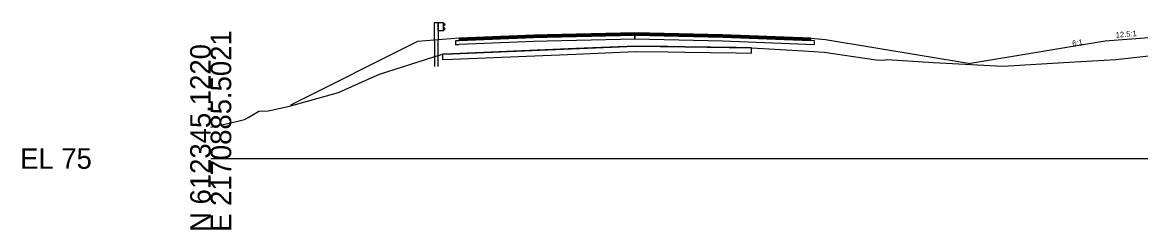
# Model space of a CAD drawing. Extents: x -26 to 1303, y -3010 to 12023.
# Drawn here: x -25.7 to 126.9, y 9990.3 to 10018.6 of the extents above; entities that cross this region are included whole.
import ezdxf

# ---------------------------------------------------------------- set-up
doc = ezdxf.new("R2010")
doc.units = 0
for name, color, linetype in [('RD_GPK_XS_Cell', 7, 'Continuous'), ('RD_PD_Final_TrvlWay', 7, 'Continuous'), ('RD_XS_Base', 7, 'Continuous'), ('RD_XS_ExGround', 7, 'Continuous'), ('RD_XS_ExPaveRet', 7, 'Continuous'), ('RD_XS_GR', 7, 'Continuous'), ('RD_XS_Greenside', 7, 'Continuous'), ('RD_XS_Pave', 7, 'Continuous'), ('RD_XS_PaveOvlay_CP', 7, 'Continuous'), ('RD_XS_TieSlope', 7, 'Continuous'), ('RD_XS_TX_ShdSlope', 7, 'Continuous'), ('RD_XS_TX_Slope', 7, 'Continuous')]:
    doc.layers.add(name, color=color, linetype=linetype)

msp = doc.modelspace()

# ---------------------------------------------------------------- linework, layer by layer
at = {"layer": 'RD_GPK_XS_Cell'}
msp.add_line((0, 10000), (150, 10000), dxfattribs=at)
at = {"layer": 'RD_PD_Final_TrvlWay'}
msp.add_lwpolyline([(31.04, 10012.56), (31.04, 10016.17), (30.54, 10016.13), (30.54, 10012.56)], dxfattribs=at)
at = {"layer": 'RD_XS_Base'}
for p, q in [((55.92, 10016.76), (45.88, 10016.56)), ((57.88, 10016.8), (55.92, 10016.76)), ((57.88, 10016.93), (57.88, 10016.96)), ((57.88, 10016.96), (57.88, 10016.85)), ((57.88, 10016.8), (57.88, 10016.96)), ((57.88, 10016.96), (57.88, 10016.96)), ((57.88, 10016.96), (57.88, 10016.96)), ((57.88, 10016.96), (57.88, 10016.3)), ((57.88, 10016.8), (57.88, 10016.93)), ((57.88, 10016.85), (57.88, 10016.3)), ((57.88, 10016.72), (57.88, 10016.8)), ((57.88, 10016.3), (57.88, 10016.8)), ((57.88, 10016.8), (57.88, 10016.8)), ((57.88, 10016.8), (57.88, 10016.8)), ((57.88, 10016.8), (57.88, 10016.8)), ((69.88, 10016.56), (57.88, 10016.8)), ((57.88, 10016.3), (57.88, 10016.72)), ((33.81, 10016.07), (33.38, 10016.06)), ((33.38, 10016.06), (33.38, 10015.99)), ((33.38, 10015.99), (33.38, 10015.56)), ((33.38, 10015.56), (33.81, 10015.57)), ((33.88, 10016.08), (33.81, 10016.07)), ((33.81, 10015.57), (33.88, 10015.58)), ((44.07, 10016.49), (33.88, 10016.08)), ((33.88, 10015.58), (44.07, 10015.99)), ((45.88, 10016.56), (44.07, 10016.49)), ((44.07, 10015.99), (45.88, 10016.06)), ((45.88, 10016.06), (55.92, 10016.26)), ((55.92, 10016.26), (57.88, 10016.3)), ((57.88, 10016.3), (57.88, 10016.3)), ((57.88, 10016.3), (57.88, 10016.3)), ((57.88, 10016.3), (69.88, 10016.06)), ((81.88, 10016.08), (69.88, 10016.56)), ((69.88, 10016.06), (82.38, 10015.56)), ((71.88, 10016.48), (71.88, 10016.48)), ((71.88, 10015.98), (71.88, 10015.98)), ((82.38, 10016.06), (81.88, 10016.08)), ((81.88, 10016.08), (81.88, 10016.08)), ((82.38, 10015.56), (82.38, 10016.06)), ((82.38, 10016.06), (82.38, 10016.06))]:
    msp.add_line(p, q, dxfattribs=at)
at = {"layer": 'RD_XS_ExGround'}
msp.add_lwpolyline([(0, 10004.26), (2.74, 10004.88), (4.59, 10005.3), (5.18, 10005.63), (6.58, 10006.44), (7.84, 10006.51), (10.76, 10007.15), (17.43, 10008.99), (21.07, 10010.64), (23.01, 10011.51), (30.42, 10013.87), (30.64, 10013.91), (31.6, 10014.23), (32.98, 10014.28), (57.91, 10015.34), (64.68, 10015.25), (73.79, 10015.11), (80.86, 10014.68), (83.68, 10014.5), (87.7, 10013.91), (90.78, 10013.47), (91.73, 10013.42), (92.27, 10013.49), (98.59, 10013.09), (108.04, 10012.6), (117.12, 10013.12), (123.46, 10013.5), (133.76, 10014.63)], dxfattribs=at)
at = {"layer": 'RD_XS_ExPaveRet'}
for points in [[(64.68, 10015.25), (62.37, 10015.28), (57.91, 10015.34), (49.83, 10015), (32.98, 10014.28), (31.6, 10014.23), (31.6, 10014.23), (31.6, 10014.23), (31.6, 10014.23), (31.6, 10013.91), (31.6, 10013.48), (31.6, 10013.48), (31.6, 10013.48), (31.6, 10013.48), (32.98, 10013.53), (49.83, 10014.25), (57.91, 10014.59), (62.37, 10014.53), (64.68, 10014.5), (71.7, 10014.39), (73.79, 10014.36), (73.79, 10014.55), (73.79, 10015.11), (71.7, 10015.14), (64.68, 10015.25)], [(64.68, 10015.25), (62.37, 10015.28), (57.91, 10015.34), (49.83, 10015), (32.98, 10014.28), (31.6, 10014.23), (31.6, 10014.23), (31.6, 10013.91), (31.6, 10013.48), (31.6, 10013.48), (32.98, 10013.53), (49.83, 10014.25), (57.91, 10014.59), (62.37, 10014.53), (64.68, 10014.5), (71.7, 10014.39), (73.79, 10014.36), (73.79, 10014.55), (73.79, 10015.11), (71.7, 10015.14), (64.68, 10015.25)]]:
    msp.add_lwpolyline(points, dxfattribs=at)
at = {"layer": 'RD_XS_GR'}
for p, q in [((30.54, 10016.13), (30.54, 10018.56)), ((30.54, 10018.56), (30.79, 10018.56)), ((30.79, 10018.56), (31.04, 10018.56)), ((31.04, 10018.56), (31.04, 10016.17)), ((31.04, 10017.4), (31.04, 10018.56)), ((31.04, 10018.56), (31.71, 10018.56)), ((31.71, 10018.56), (31.71, 10017.4)), ((31.75, 10018.52), (31.71, 10018.56)), ((31.71, 10018.56), (31.71, 10018.4)), ((31.71, 10018.4), (31.71, 10017.4)), ((31.71, 10017.98), (31.95, 10018.23)), ((31.98, 10018.27), (31.75, 10018.52)), ((31.95, 10018.23), (31.98, 10018.27)), ((31.71, 10017.4), (31.04, 10017.4)), ((31.75, 10017.94), (31.71, 10017.98)), ((31.71, 10017.4), (31.95, 10017.65)), ((31.98, 10017.69), (31.75, 10017.94)), ((31.95, 10017.65), (31.98, 10017.69)), ((31.04, 10016.17), (30.54, 10016.13))]:
    msp.add_line(p, q, dxfattribs=at)
at = {"layer": 'RD_XS_Greenside'}
for p, q in [((28.23, 10015.94), (10.9, 10007.28)), ((83.88, 10016.24), (103.67, 10012.94)), ((122, 10015.99), (103.67, 10012.94))]:
    msp.add_line(p, q, dxfattribs=at)
at = {"layer": 'RD_XS_Pave'}
for p, q in [((44.07, 10016.8), (33.88, 10016.4)), ((45.88, 10016.88), (44.07, 10016.8)), ((45.88, 10016.72), (44.07, 10016.64)), ((44.07, 10016.64), (45.88, 10016.72)), ((55.92, 10017.08), (45.88, 10016.88)), ((55.92, 10016.92), (45.88, 10016.72)), ((45.88, 10016.72), (55.92, 10016.92)), ((45.88, 10016.56), (55.92, 10016.76)), ((57.88, 10017.12), (55.92, 10017.08)), ((57.88, 10016.96), (55.92, 10016.92)), ((55.92, 10016.92), (57.88, 10016.96)), ((55.92, 10016.76), (57.88, 10016.8)), ((69.88, 10016.88), (57.88, 10017.12)), ((57.88, 10017.12), (57.88, 10017.12)), ((57.88, 10017.12), (57.88, 10017.12)), ((57.88, 10016.93), (57.88, 10016.96)), ((57.88, 10016.96), (57.88, 10016.93)), ((57.88, 10016.8), (57.88, 10016.96)), ((57.88, 10016.96), (57.88, 10016.96)), ((57.88, 10016.96), (57.88, 10016.96)), ((57.88, 10016.96), (57.88, 10016.96)), ((57.88, 10016.96), (57.88, 10016.96)), ((57.88, 10016.96), (69.88, 10016.72)), ((69.88, 10016.72), (57.88, 10016.96)), ((57.88, 10016.96), (57.88, 10016.96)), ((57.88, 10016.96), (57.88, 10016.96)), ((57.88, 10016.96), (57.88, 10016.8)), ((57.88, 10016.8), (57.88, 10016.93)), ((57.88, 10016.93), (57.88, 10016.8)), ((57.88, 10016.8), (57.88, 10016.8)), ((57.88, 10016.8), (57.88, 10016.8)), ((57.88, 10016.8), (69.88, 10016.56)), ((81.88, 10016.4), (69.88, 10016.88)), ((69.88, 10016.72), (81.88, 10016.24)), ((81.88, 10016.24), (69.88, 10016.72)), ((71.88, 10016.8), (71.88, 10016.8)), ((44.07, 10016.64), (33.88, 10016.24)), ((33.88, 10016.24), (44.07, 10016.64)), ((33.88, 10016.08), (44.07, 10016.49)), ((33.88, 10016.4), (33.88, 10016.37)), ((33.88, 10016.37), (33.88, 10016.24)), ((33.88, 10016.24), (33.88, 10016.21)), ((33.88, 10016.21), (33.88, 10016.08)), ((44.07, 10016.49), (45.88, 10016.56)), ((69.88, 10016.56), (81.88, 10016.08)), ((71.88, 10016.64), (71.88, 10016.64)), ((71.88, 10016.64), (71.88, 10016.64)), ((71.88, 10016.48), (71.88, 10016.48)), ((81.88, 10016.24), (81.88, 10016.4)), ((81.88, 10016.4), (81.88, 10016.4)), ((81.88, 10016.08), (81.88, 10016.24)), ((81.88, 10016.24), (81.88, 10016.24))]:
    msp.add_line(p, q, dxfattribs=at)
at = {"layer": 'RD_XS_PaveOvlay_CP'}
for p, q in [((33.88, 10016.4), (45.88, 10016.88)), ((45.88, 10016.88), (57.88, 10017.12)), ((57.88, 10017.12), (69.88, 10016.88)), ((69.88, 10016.88), (81.88, 10016.4))]:
    msp.add_line(p, q, dxfattribs=at)
at = {"layer": 'RD_XS_TieSlope'}
for p, q in [((33.88, 10016.4), (28.23, 10015.94)), ((81.88, 10016.4), (83.88, 10016.24)), ((128, 10016.47), (122, 10015.99))]:
    msp.add_line(p, q, dxfattribs=at)

# ---------------------------------------------------------------- texts
at = {"layer": 'RD_GPK_XS_Cell'}
for s, p in [('E 2170885.5021', (2.8, 9990)), ('N 612345.1220', (0, 9990))]:
    msp.add_text(s, height=2.8, rotation=90, dxfattribs=at).set_placement(p)
msp.add_text('EL 75', height=2.8, dxfattribs=at).set_placement((-26, 9998.6))
at = {"layer": 'RD_XS_TX_ShdSlope'}
msp.add_text('12.5:1', height=0.75, rotation=4.5739, dxfattribs=at).set_placement((123.49, 10016.47))
at = {"layer": 'RD_XS_TX_Slope'}
msp.add_text('6:1', height=0.75, rotation=9.4623, dxfattribs=at).set_placement((117.59, 10015.31))

doc.saveas('drawing.dxf')
